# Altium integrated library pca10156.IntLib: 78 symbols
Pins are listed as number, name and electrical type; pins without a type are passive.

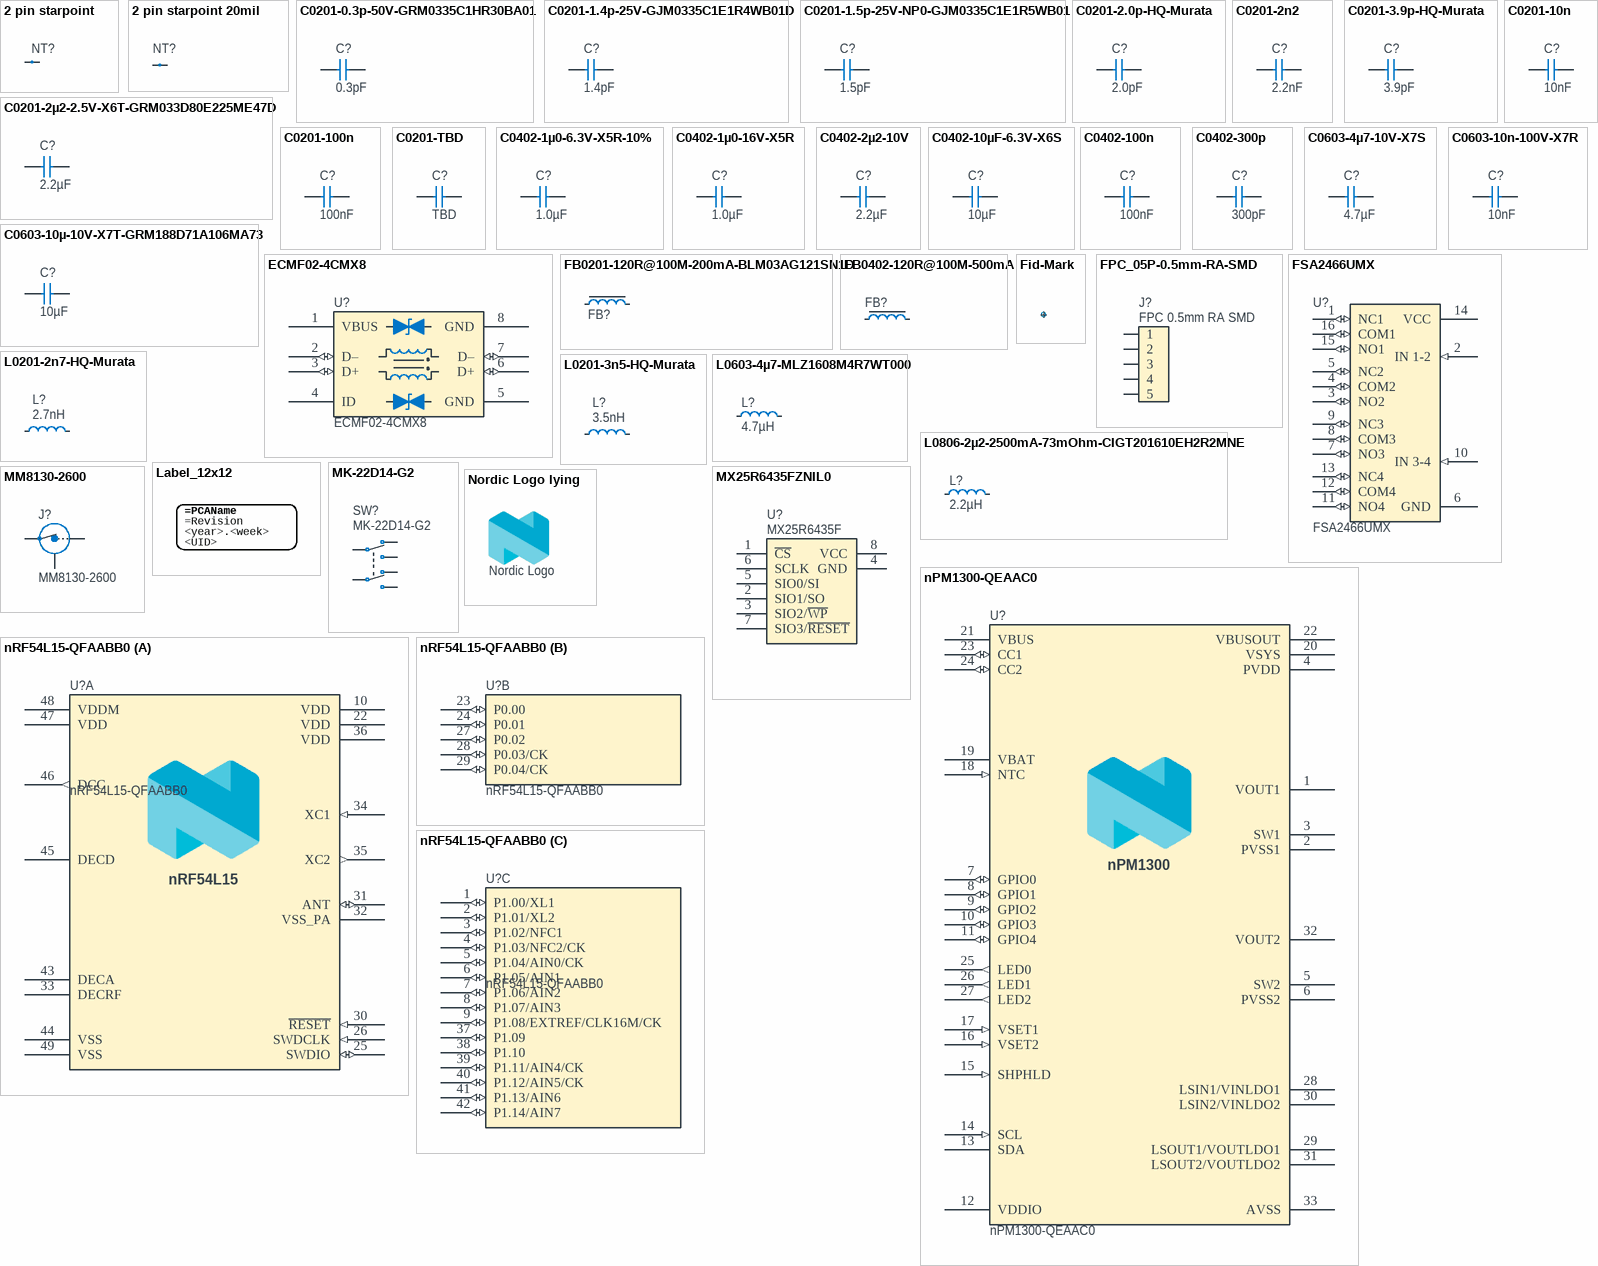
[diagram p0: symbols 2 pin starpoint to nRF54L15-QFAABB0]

## 2 pin starpoint
designator NT?, comment Net tie  (value not drawn)  (net tie, no BOM)
Starpoint; Part Number: 2 pin starpoint; Manufacturer: N.A.; Part number NEMS: 100500603; Pad Count: 2; Component Status: Active; System: Connector
footprint 2 PIN STARPOINT
pins: 1, 2

## 2 pin starpoint 20mil
designator NT?, comment N.A.  (value not drawn)  (net tie, no BOM)
Starpoint; Part Number: 2 pin starpoint 20mil; Part number NEMS: 100500717; Component Status: Active; Pad Count: 2; System: Connector
footprint 2 pin starpoint 20mil
pins: 1, 2

## C0201-0.3p-50V-GRM0335C1HR30BA01
designator C?, comment 0.3pF
Capacitor, C0G, ±0.1pF, 50V; Part Number: C0201-0.3p-50V-GRM0335C1HR30BA01; Manufacturer: Murata; Manufacturer Part Number: GRM0335C1HR30BA01; Part number NEMS: 100200650; Component Status: Active; Pad Count: 2; Artikkelnr Noca: N.A.
footprint CAPC0603X03L_C
pins: 1, 2

## C0201-1.4p-25V-GJM0335C1E1R4WB01D
designator C?, comment 1.4pF
Capacitor, C0G, ±0.05pF, 25V; Part Number: C0201-1.4p-25V-GJM0335C1E1R4WB01D; Manufacturer: Murata; Manufacturer Part Number: GJM0335C1E1R4WB01D; Part number NEMS: 100200553; Pad Count: 2; Artikkelnr Noca: N.A.; Component Status: Active
footprint CAPC0603X03L_C
pins: 1, 2

## C0201-1.5p-25V-NP0-GJM0335C1E1R5WB01
designator C?, comment 1.5pF
Capacitor, NP0, ±0.05pF, 25V, High Q; Part Number: C0201-1.5p-25V-NP0-GJM0335C1E1R5WB01; Manufacturer: Murata; Manufacturer Part Number: GJM0335C1E1R5WB01; Part number NEMS: 100200477; Component Status: Active; Pad Count: 2; Artikkelnr Noca: N.A.
footprint CAPC0603X03L_C
pins: 1, 2

## C0201-2.0p-HQ-Murata
designator C?, comment 2.0pF
Capacitor, NP0, ±0.05pF, 25V; Part Number: C0201-2.0p-HQ-Murata; Manufacturer: Murata; Manufacturer Part Number: GJM0335C1E2R0WB01; Part number IPS: 00000001775; Part number NEMS: 100200419; Component Status: Active; Pad Count: 2; Artikkelnr Noca: N.A.
footprint CAPC0603X03L_C
pins: 1, 2

## C0201-2n2
designator C?, comment 2.2nF
Capacitor, X7R, ±10%, 10V; Part Number: C0201-2n2; Manufacturer: N.A.; Part number IPS: 00000001778; Part number Norautron: 26470002; Part number NEMS: 100200060; Pad Count: 2; Component Status: Active
footprint CAPC0603X03L_C
pins: 1, 2

## C0201-2µ2-2.5V-X6T-GRM033D80E225ME47D
designator C?, comment 2.2µF
Capacitor, Ceramic, 2.2µF 2.5V X6T 0201,±20%; Part Number: C0201-2µ2-2.5V-X6T-GRM033D80E225ME47D; Manufacturer: Murata; Manufacturer Part Number: GRM033R61A225KE47; Part number NEMS: 100200527; Component Status: Active; Pad Count: 2; Note: 2.5V, 20%, X6T; Artikkelnr Noca: N.A.
footprint CAPC0603X03L_C
pins: 1, 2

## C0201-3.9p-HQ-Murata
designator C?, comment 3.9pF
Capacitor, NP0, ±0.05pF, 25V; Part Number: C0201-3.9p-HQ-Murata; Manufacturer: Murata; Manufacturer Part Number: GJM0333C1E3R9WB01; Part number NEMS: 100200424; Component Status: Active; Pad Count: 2; Artikkelnr Noca: N.A.
footprint CAPC0603X03L_C
pins: 1, 2

## C0201-10n
designator C?, comment 10nF
Capacitor, X7R, ±10%; Part Number: C0201-10n; Manufacturer: N.A.; Part number IPS: 00000003480; Part number Norautron: 26621779; Part number NEMS: 100200067; Note: 10V; Pad Count: 2; Component Status: Active
footprint CAPC0603X03L_C
pins: 1, 2

## C0201-100n
designator C?, comment 100nF
Capacitor, X5R, ±10%; Part Number: C0201-100n; Manufacturer: N.A.; Part number IPS: 00000001248, 00000002505; Part number Norautron: 262071862; Part number NEMS: 100200078; Pad Count: 2; Note: 16V; Component Status: Active
footprint CAPC0603X03L_C
pins: 1, 2

## C0201-TBD
designator C?, comment TBD
Chip Cap 0201; Part Number: C0201-TBD; Manufacturer: N.A.; Part number NEMS: 100200002; Component Status: Active; Pad Count: 2; Assembly: Not Mounted
footprint CAPC0603X03L_C
pins: 1, 2

## C0402-1µ0-6.3V-X5R-10%
designator C?, comment 1.0µF
Capacitor, X5R, ±10%, 6.3V; Part Number: C0402-1µ0-6.3V-X5R-10%; Manufacturer: N.A.; Part number Norautron: 26207137; Part number NEMS: 100200498; Pad Count: 2; Component Status: Active
footprint CAPC1005X04L
pins: 1, 2

## C0402-1µ0-16V-X5R
designator C?, comment 1.0µF
Capacitor, Ceramic, X5R, ±10%, 16V; Part Number: C0402-1µ0-16V-X5R; Manufacturer: Murata; Manufacturer Part Number: GRT155R61C105KE01D; Part number NEMS: 100200452; Component Status: Active; Pad Count: 2; Artikkelnr Noca: N.A.
footprint CAPC1005X04L
pins: 1, 2

## C0402-2µ2-10V
designator C?, comment 2.2µF
Capacitor, X5R, ±10%; Part Number: C0402-2µ2-10V; Manufacturer: N.A.; Part number NEMS: 100200376; Component Status: Active; Pad Count: 2; Note: 10V
footprint CAPC1005X04L
pins: 1, 2

## C0402-10µF-6.3V-X6S
designator C?, comment 10µF
Capacitor, X6S, ±20%, 6.3V; Part Number: C0402-10µF-6.3V-X6S; Manufacturer: N.A.; Part number NEMS: 100200478; Component Status: Active; Pad Count: 2
footprint CAPC1005X04L
pins: 1, 2

## C0402-100n
designator C?, comment 100nF
Capacitor, X7R, ±10%; Part Number: C0402-100n; Manufacturer: N.A.; Part number IPS: 00000005296; Part number NEMS: 100200184; Component Status: Active; Pad Count: 2; Note: 16V; Artikkelnr Noca: 20039200; Assembly: Not Mounted
footprint CAPC1005X04L
pins: 1, 2

## C0402-300p
designator C?, comment 300pF
Capacitor, C0G, ±5%, 50V; Part Number: C0402-300p; Manufacturer: N.A.; Part number IPS: 00000007788; Part number NEMS: 100200155; Artikkelnr Noca: 20020004; Pad Count: 2; Component Status: Active
footprint CAPC1005X04L
pins: 1, 2

## C0603-4µ7-10V-X7S
designator C?, comment 4.7µF
Capacitor, X7S, ±10%, 10V; Part Number: C0603-4µ7-10V-X7S; Manufacturer: N.A.; Part number IPS: 00000001779; Part number NEMS: 100200351; Pad Count: 2; Artikkelnr Noca: 20030013; Component Status: Active
footprint CAPC1608X06L
pins: 1, 2

## C0603-10n-100V-X7R
designator C?, comment 10nF
Capacitor, X7R, ±10%, 100V; Part Number: C0603-10n-100V-X7R; Manufacturer: Murata; Manufacturer Part Number: GCM188R72A103KA37D; Part number NEMS: 100200349; Component Status: Active; Pad Count: 2; Artikkelnr Noca: N.A.
footprint CAPC1608X06L
pins: 1, 2

## C0603-10µ-10V-X7T-GRM188D71A106MA73
designator C?, comment 10µF
Capacitor, X7T, ±20%, 10V; Part Number: C0603-10µ-10V-X7T-GRM188D71A106MA73; Manufacturer: Murata; Manufacturer Part Number: GRM188D71A106MA73; Part number IPS: 00000004696; Part number NEMS: 100200414; Component Status: Active; Pad Count: 2; Note: 10VDC; Artikkelnr Noca: N.A.
footprint CAPC1608X06L
pins: 1, 2

## ECMF02-4CMX8
designator U?
2 Line Common mode filter with ESD protection for USB 2.0 interface; Manufacturer: STMicroelectronics; Part number NEMS: 100800034; Component Status: Active; Pad Count: 8; Note: N.A.
footprint UFDFN50P120X250X55-8N
pins: 1 VBUS (power), 2 D– (io), 3 D+ (io), 4 ID, 5 GND (power), 6 D+ (io), 7 D– (io), 8 GND (power)

## FB0201-120R@100M-200mA-BLM03AG121SN1D
designator FB?, comment 120R/0.2A  (value not drawn)
Ferrite Bead, 120 Ohm @ 100MHz, 200mA, 500 mOhm Max; Part Number: FB0201-120R@100M-200mA-BLM03AG121SN1D; Manufacturer: Murata; Manufacturer Part Number: BLM03AG121SN1D; Part number NEMS: 100300419; Component Status: Active; Pad Count: 2; Artikkelnr Noca: N.A.
footprint INDC0603X03L_C
pins: 1, 2

## FB0402-120R@100M-500mA
designator FB?, comment 120R/0.55A  (value not drawn)
Ferrite Bead, 120 Ohm @ 100MHz, 500mA, 250 mOhm Max; Part Number: FB0402-120R@100M-500mA; Manufacturer: Murata; Manufacturer Part Number: BLM15AG121SN1D; Part number IPS: 00000009954; Part number Norautron: 265230631; Part number NEMS: 100300099; Note: Chip EMIFIL Inductor Type Chip Ferrite Bead; Artikkelnr Noca: 33029317; Pad Count: 2; Component Status: Active
footprint INDC1005X04L
pins: 1, 2

## Fid-Mark
designator Fid?, comment Fiducial mark  (value not drawn)
Part Number: Fid-Mark; Manufacturer: N.A.; Part number NEMS: 100500073; Value: N.A.; Pad Count: 1; Component Status: Active; System: Connector
footprint Fiducial

## FPC_05P-0.5mm-RA-SMD
designator J?, comment FPC 0.5mm RA SMD
0.5mm FPC, 5P,Right Angle SMT,Double Contact,H=1.2mm,White, Tin plated; Part Number: FPC_05P-0.5mm-RA-SMD; Manufacturer: WCON; Manufacturer Part Number: 5141-05RZDNWR03; Part number NEMS: 100500528; Note: (Replaced 5141-05RZDNWR02); Artikkelnr Noca: N.A.; Pad Count: 7; Component Status: Active; System: Connector
footprint FPC_05P-0.5mm-RA-SMD
pins: 1, 2, 3, 4, 5

## FSA2466UMX
designator U?
Data / Audio Low-Voltage Dual DPDT Analog Switch; Manufacturer: ON Semiconductor; Part number IPS: 00000009986; Part number Norautron: 26500608; Part number NEMS: 101900422; Note: N.A.; Artikkelnr Noca: 15070069; Pad Count: 16; Component Status: Active
footprint XQFN40P180X260X50-16N
pins: 1 NC1 (io), 2 IN 1-2 (in), 3 NO2 (io), 4 COM2 (io), 5 NC2 (io), 6 GND (power), 7 NO3 (io), 8 COM3 (io), 9 NC3 (io), 10 IN 3-4 (in), 11 NO4 (io), 12 COM4 (io), 13 NC4 (io), 14 VCC (power), 15 NO1 (io), 16 COM1 (io)
1 alternate drawing of the same symbol

## L0201-2n7-HQ-Murata
designator L?, comment 2.7nH
Inductor, 600mA, ±0.1ｎH, 120mOhm; Part Number: L0201-2n7-HQ-Murata; Manufacturer: Murata; Manufacturer Part Number: LQP03HQ2N7B02; Part number IPS: 00000001753; Part number NEMS: 100300214; Component Status: Active; Pad Count: 2; Note: -55°C ~ 125°C; Artikkelnr Noca: N.A.
footprint INDC0603X03L_C
pins: 1, 2

## L0201-3n5-HQ-Murata
designator L?, comment 3.5nH
Inductor, 500mA, ±0.1ｎH, 170mOhm; Part Number: L0201-3n5-HQ-Murata; Manufacturer: Murata; Manufacturer Part Number: LQP03HQ3N5B02; Part number NEMS: 100300222; Component Status: Active; Pad Count: 2; Note: -55°C ~ 125°C; Artikkelnr Noca: N.A.
footprint INDC0603X03L_C
pins: 1, 2

## L0603-4µ7-MLZ1608M4R7WT000
designator L?, comment 4.7µH
Inductor, 120mA, ±20%, 0.65R; Part Number: L0603-4µ7-MLZ1608M4R7WT000; Manufacturer: TDK Corporation; Manufacturer Part Number: MLZ1608M4R7WT000; Part number NEMS: 100300440; Component Status: Active; Pad Count: 2; Note: Power Inductor ±20%; Artikkelnr Noca: N.A.
footprint INDC1608X06L
pins: 1, 2

## L0806-2µ2-2500mA-73mOhm-CIGT201610EH2R2MNE
designator L?, comment 2.2µH
Inductor, Irms=2.5A, Isat=2.9A, ±20%, DCR=73mΩ; Part Number: L0806-2µ2-2500mA-73mOhm-CIGT201610EH2R2MNE; Manufacturer: Samsung Electro-Mechanics America; Manufacturer Part Number: CIGT201610EH2R2MNE; Part number Norautron: 26521789; Part number NEMS: 100300400; Component Status: Active; Pad Count: 2; Note: Unshielded Thin Film Inductor; Artikkelnr Noca: N.A.
footprint INDC2016X10N
pins: 1, 2

## Label_12x12
designator LABEL?, comment 12x12mm  (value not drawn)
PCA version label, stick-on, 12x12mm; Part Number: Label_12x12; Manufacturer: Ellco Etikett; Manufacturer Part Number: A33512‐01; Part number NEMS: 101200028; Component Status: Active; Pad Count: 0; Note: N.A.
footprint LabelSilk_12x12

## MK-22D14-G2
designator SW?
Slide Switch DPDT; Manufacturer: HUA-JIE CORP.; Part number NEMS: 101500131; Note: N.A.; Pad Count: 6; Component Status: Active
footprint MK-22D14-G2
pins: 1 N.O-1, 2 COM-1, 3 N.C-1, 4 N.O-2, 5 COM-2, 6 N.C-2

## MM8130-2600
designator J?
Coaxial Connector with Switch; Manufacturer: Murata; Part number IPS: 00000009955; Part number Norautron: 26030338; Part number NEMS: 100500400; Component Status: Active; Pad Count: 3; Note: N.A.; Artikkelnr Noca: 55029011
footprint COAXIAL-SWF
pins: 1 IN, 2 Shield, 3 OUT

## MX25R6435FZNIL0
designator U?, comment MX25R6435F
Ultra low power, 64M-bit, serial multi I/O flash memory; Part Number: MX25R6435FZNIL0; Manufacturer: Macronix; Part number IPS: 00000004370; Part number NEMS: 101900438; Note: N.A.; Artikkelnr Noca: 15020015; Pad Count: 8; Component Status: Active
footprint SON127P600X80_HS-9N
pins: 1 ~{CS}, 2 SIO1/SO, 3 SIO2/~{WP}, 4 GND, 5 SIO0/SI, 6 SCLK, 7 SIO3/~{RESET}, 8 VCC, 9 GND hidden to GND

## Nordic Logo lying
designator LOGO?, comment Nordic Logo  (no BOM)
Nordic logo lying; Manufacturer: N.A.; Part number NEMS: 101100001; Component Status: Active; Pad Count: 0
footprint NORDIC_LOGO_LYING

## nPM1300-QEAAC0
designator U?
Li-Ion/Li-Polymer USB-C battery charger with high efficiency buck regulators, LDOs or load switches, LED drivers, TWI and VBUSOUT; Manufacturer: Nordic Semiconductor; Part number NEMS: 102000306; Component Status: Active; Pad Count: 33; Note: Production version; Artikkelnr Noca: N.A.
footprint Nordic_QFN50P500X500X90-33N
pins: 1 VOUT1 (power), 2 PVSS1 (power), 3 SW1 (power), 4 PVDD (power), 5 SW2 (power), 6 PVSS2 (power), 7 GPIO0 (io), 8 GPIO1 (io), 9 GPIO2 (io), 10 GPIO3 (io), 11 GPIO4 (io), 12 VDDIO (power), 13 SDA (oc), 14 SCL (in), 15 SHPHLD (in), 16 VSET2 (in), 17 VSET1 (in), 18 NTC (in), 19 VBAT, 20 VSYS (power), 21 VBUS (power), 22 VBUSOUT (power), 23 CC1 (io), 24 CC2 (io), 25 LED0 (out), 26 LED1 (out), 27 LED2 (out), 28 LSIN1/VINLDO1 (power), 29 LSOUT1/VOUTLDO1 (power), 30 LSIN2/VINLDO2 (power), 31 LSOUT2/VOUTLDO2 (power), 32 VOUT2 (power), 33 AVSS (power)

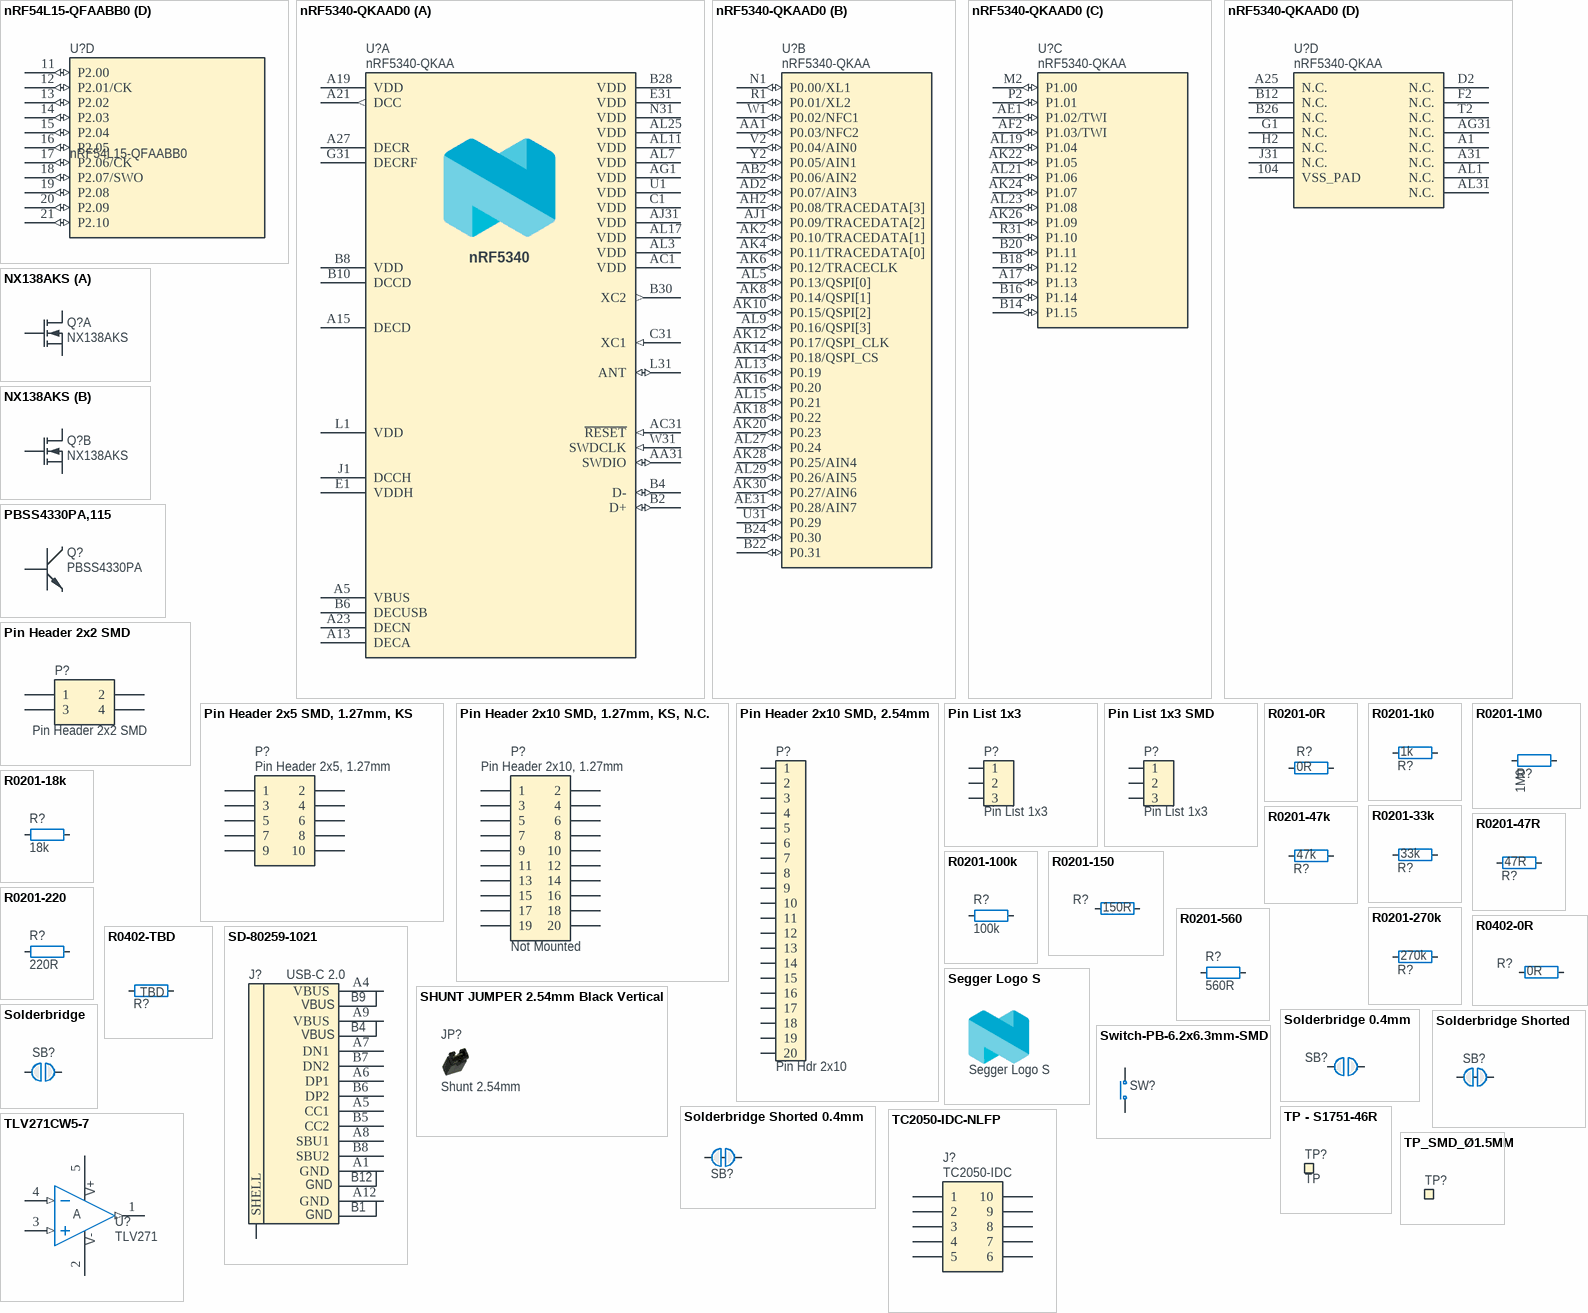
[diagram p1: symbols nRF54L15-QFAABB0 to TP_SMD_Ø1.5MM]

## nRF54L15-QFAABB0
designator U?
Multi-protocol Bluetooth Low Energy, IEEE 802.15.4, ANT and 2.4GHz proprietary system-on-chip; Manufacturer: Nordic Semiconductor; Component Status: Active; Pad Count: 49; Note: N.A.
footprint QFN40P600X600X90-48N
part A pins: 10 VDD (power), 22 VDD (power), 25 SWDIO (io), 26 SWDCLK (in), 30 ~{RESET} (in), 31 ANT (io), 32 VSS_PA (power), 33 DECRF (power), 34 XC1 (in), 35 XC2 (out), 36 VDD (power), 43 DECA (power), 44 VSS (power), 45 DECD (power), 46 DCC (out), 47 VDD (power), 48 VDDM (power), 49 VSS (power)
part B pins: 23 P0.00 (io), 24 P0.01 (io), 27 P0.02 (io), 28 P0.03/CK (io), 29 P0.04/CK (io)
part C pins: 1 P1.00/XL1 (io), 2 P1.01/XL2 (io), 3 P1.02/NFC1 (io), 4 P1.03/NFC2/CK (io), 5 P1.04/AIN0/CK (io), 6 P1.05/AIN1 (io), 7 P1.06/AIN2 (io), 8 P1.07/AIN3 (io), 9 P1.08/EXTREF/CLK16M/CK (io), 37 P1.09 (io), 38 P1.10 (io), 39 P1.11/AIN4/CK (io), 40 P1.12/AIN5/CK (io), 41 P1.13/AIN6 (io), 42 P1.14/AIN7 (io)
part D pins: 11 P2.00 (io), 12 P2.01/CK (io), 13 P2.02 (io), 14 P2.03 (io), 15 P2.04 (io), 16 P2.05 (io), 17 P2.06/CK (io), 18 P2.07/SWO (io), 19 P2.08 (io), 20 P2.09 (io), 21 P2.10 (io)

## nRF5340-QKAAD0
designator U?, comment nRF5340-QKAA
Multi-protocol Bluetooth Low Energy, IEEE 802.15.4, ANT and 2.4GHz proprietary system-on-chip; Part Number: nRF5340-QKAAD0; Manufacturer: Nordic Semiconductor; Part number Norautron: NOD26470035; Part number NEMS: 102000216; Pad Count: 98; Note: N.A.; Component Status: Active
footprint AQFN40P700X700X85_HS-99N
part A pins: A5 VBUS (power), A13 DECA (power), A15 DECD (power), A19 VDD (power), A21 DCC (out), A23 DECN (power), A27 DECR (power), AA31 SWDIO (io), AC1 VDD (power), AC31 ~{RESET} (in), AG1 VDD (power), AJ31 VDD (power), AL3 VDD (power), AL7 VDD (power), AL11 VDD (power), AL17 VDD (power), AL25 VDD (power), B2 D+ (io), B4 D- (io), B6 DECUSB (power), B8 VDD (power), B10 DCCD (power), B28 VDD (power), B30 XC2 (out), C1 VDD (power), C31 XC1 (in), E1 VDDH (power), E31 VDD (power), G31 DECRF (power), J1 DCCH (power), L1 VDD (power), L31 ANT (io), N31 VDD (power), U1 VDD (power), W31 SWDCLK (in)
part B pins: AA1 P0.03/NFC2 (io), AB2 P0.06/AIN2 (io), AD2 P0.07/AIN3 (io), AE31 P0.28/AIN7 (io), AH2 P0.08/TRACEDATA[3] (io), AJ1 P0.09/TRACEDATA[2] (io), AK2 P0.10/TRACEDATA[1] (io), AK4 P0.11/TRACEDATA[0] (io), AK6 P0.12/TRACECLK (io), AK8 P0.14/QSPI[1] (io), AK10 P0.15/QSPI[2] (io), AK12 P0.17/QSPI_CLK (io), AK14 P0.18/QSPI_CS (io), AK16 P0.20 (io), AK18 P0.22 (io), AK20 P0.23 (io), AK28 P0.25/AIN4 (io), AK30 P0.27/AIN6 (io), AL5 P0.13/QSPI[0] (io), AL9 P0.16/QSPI[3] (io), AL13 P0.19 (io), AL15 P0.21 (io), AL27 P0.24 (io), AL29 P0.26/AIN5 (io), B22 P0.31 (io), B24 P0.30 (io), N1 P0.00/XL1 (io), R1 P0.01/XL2 (io), U31 P0.29 (io), V2 P0.04/AIN0 (io), W1 P0.02/NFC1 (io), Y2 P0.05/AIN1 (io)
part C pins: A17 P1.13 (io), AE1 P1.02/TWI (io), AF2 P1.03/TWI (io), AK22 P1.05 (io), AK24 P1.07 (io), AK26 P1.09 (io), AL19 P1.04 (io), AL21 P1.06 (io), AL23 P1.08 (io), B14 P1.15 (io), B16 P1.14 (io), B18 P1.12 (io), B20 P1.11 (io), M2 P1.00 (io), P2 P1.01 (io), R31 P1.10 (io)
part D pins: 104 VSS_PAD (power), A1 N.C., A25 N.C., A31 N.C., AG31 N.C., AL1 N.C., AL31 N.C., B12 N.C., B26 N.C., D2 N.C., F2 N.C., G1 N.C., H2 N.C., J31 N.C., T2 N.C.

## NX138AKS
designator Q?
MOSFET 2N-CH 60V 0.17A TSSOP6 (SOT363); Manufacturer: Nexperia; Manufacturer Part Number: NX138AKSX; Part number NEMS: 101300207; Component Status: Active; Pad Count: 6; Note: N.A.
footprint TSSOP6
part A pins: 1 S1, 2 G1, 6 D1
part B pins: 3 D2, 4 S2, 5 G2

## PBSS4330PA,115
designator Q?, comment PBSS4330PA
30V, 3A, 2.1W, G=270, NPN Transistor; Part Number: PBSS4330PA,115; Manufacturer: Nexperia; Part number NEMS: 101300184; Component Status: Active; Pad Count: 3; Note: N.A.
footprint DFN105P200X65-3N_v2
pins: 1 B, 2 E (power), 3 C (power)

## Pin Header 2x2 SMD
designator P?
Pin Header 2x2, SMD, 2.54mm (100mil); Manufacturer: WCON; Manufacturer Part Number: 1125-1202S0M116CR03; Part number NEMS: 100500770; Component Status: Active; Pad Count: 4; Note: N.A.; System: Connector
footprint HDR_2x2-SMD
pins: 1, 2, 3, 4

## Pin Header 2x5 SMD, 1.27mm, KS
designator P?, comment Pin Header 2x5, 1.27mm
Pin Header 2x5, 1.27mm (50mil), SMD, Keying Shroud; Part Number: Pin Header 2x5 SMD, 1.27mm, KS; Manufacturer: WCON; Manufacturer Part Number: 3132-10MS0BK00R5; Part number NEMS: 100500261; Note: (Replaced 3132-10MS0BK00R1); Artikkelnr Noca: N.A.; Pad Count: 10; Component Status: Active; System: Connector
footprint HDR_2x5-SMD-1.27mm-K
pins: 1, 2, 3, 4, 5, 6, 7, 8, 9, 10

## Pin Header 2x10 SMD, 1.27mm, KS, N.C.
designator P?, comment Pin Header 2x10, 1.27mm  Assembly: Not Mounted
Pin Header 2x10, 1.27mm (50mil), SMD, Keying Shroud; Part Number: Pin Header 2x10 SMD, 1.27mm, KS, N.C.; Manufacturer: WCON; Manufacturer Part Number: 3132-20MS0BK00R1; Part number NEMS: 100500279; Note: N.A.; Pad Count: 20; Component Status: Active; System: Connector
footprint HDR_2x10-SMD-1.27mm-NC
pins: 1, 2, 3, 4, 5, 6, 7, 8, 9, 10, 11, 12, 13, 14, 15, 16, 17, 18, 19, 20

## Pin Header 2x10 SMD, 2.54mm
designator P?, comment Pin Hdr 2x10
Pin Header 2x10, 2.54mm (100mil) SMD; Part Number: Pin Header 2x10 SMD, 2.54mm; Manufacturer: WCON; Manufacturer Part Number: 1125-1210S0M116CR09; Part number NEMS: 100500738; Pad Count: 20; Artikkelnr Noca: N.A.; Component Status: Active; System: Connector
footprint HDR_2x10-SMD
pins: 1, 2, 3, 4, 5, 6, 7, 8, 9, 10, 11, 12, 13, 14, 15, 16, 17, 18, 19, 20
1 alternate drawing of the same symbol

## Pin List 1x3
designator P?
Pin List 1x3, 2.54mm (100mil); Manufacturer: N.A.; Part number NEMS: 100500304; Component Status: Active; Pad Count: 3; Artikkelnr Noca: 56019041; Assembly: Not Mounted; System: Connector
footprint LIST_1x3
pins: 1, 2, 3

## Pin List 1x3 SMD
designator P?, comment Pin List 1x3
Pin List 1x3, 2.54mm (100mil), SMD; Part Number: Pin List 1x3 SMD; Manufacturer: WCON; Manufacturer Part Number: 1125-1103S0M116CR04; Part number Norautron: 26470016; Part number NEMS: 100500306; Note: N.A.; Pad Count: 3; Component Status: Active; System: Connector
footprint LIST_1x3_SMD
pins: 1, 2, 3

## R0201-0R
designator R?, comment 0R
Resistor, ±5%, 0.05W; Part Number: R0201-0R; Manufacturer: N.A.; Part number IPS: 00000003245; Part number NEMS: 100100001; Component Status: Active; Pad Count: 2; Note: Chip Res 5%
footprint RESC0603X03L_C
pins: 1, 2

## R0201-1k0
designator R?, comment 1k
Resistor, ±1%, 0.05W; Part Number: R0201-1k0; Manufacturer: N.A.; Part number IPS: 00000005786; Part number NEMS: 100100043; Component Status: Active; Pad Count: 2; Note: Chip Res 1%
footprint RESC0603X03L_C
pins: 1, 2

## R0201-1M0
designator R?, comment 1M0
Resistor, ±1%, 0.05W; Part Number: R0201-1M0; Manufacturer: N.A.; Part number IPS: 00000001418; Part number Norautron: 26107108; Part number NEMS: 100100093; Component Status: Active; Pad Count: 2; Note: Chip Res 1%
footprint RESC0603X03L_C
pins: 1, 2

## R0201-18k
designator R?, comment 18k
Resistor, ±1%, 0.05W; Part Number: R0201-18k; Manufacturer: N.A.; Part number IPS: 00000001707; Part number NEMS: 100100069; Component Status: Active; Pad Count: 2; Note: Chip Res 1%; Assembly: Not Mounted
footprint RESC0603X03L_C
pins: 1, 2

## R0201-33k
designator R?, comment 33k
Resistor, ±1%, 0.05W; Part Number: R0201-33k; Manufacturer: N.A.; Part number IPS: 00000001708; Part number NEMS: 100100073; Component Status: Active; Pad Count: 2; Note: Chip Res 1%
footprint RESC0603X03L_C
pins: 1, 2

## R0201-47k
designator R?, comment 47k
Resistor, ±1%, 0.05W; Part Number: R0201-47k; Manufacturer: N.A.; Part number IPS: 00000001423; Part number NEMS: 100100076; Component Status: Active; Pad Count: 2; Note: Chip Res 1%
footprint RESC0603X03L_C
pins: 1, 2

## R0201-47R
designator R?, comment 47R
Resistor, ±1%, 0.05W; Part Number: R0201-47R; Manufacturer: N.A.; Part number IPS: 00000004794; Part number Norautron: 26108300; Part number NEMS: 100100022; Component Status: Active; Pad Count: 2; Note: Chip Res 1%
footprint RESC0603X03L_C
pins: 1, 2

## R0201-100k
designator R?, comment 100k
Resistor, ±1%, 0.05W; Part Number: R0201-100k; Manufacturer: N.A.; Part number IPS: 00000001419; Part number Norautron: 26108487; Part number NEMS: 100100080; Note: Chip Res 1%; Pad Count: 2; Component Status: Active
footprint RESC0603X03L_C
pins: 1, 2

## R0201-150
designator R?, comment 150R
Resistor, ±1%, 0.05W; Part Number: R0201-150; Manufacturer: N.A.; Part number IPS: 00000001420; Part number NEMS: 100100029; Note: Chip Res 1%; Pad Count: 2; Component Status: Active
footprint RESC0603X03L_C
pins: 1, 2

## R0201-220
designator R?, comment 220R
Resistor, ±1%, 0.05W; Part Number: R0201-220; Manufacturer: N.A.; Part number IPS: 00000000863; Part number Norautron: 26107014; Part number NEMS: 100100032; Note: Chip Res 1%; Pad Count: 2; Component Status: Active
footprint RESC0603X03L_C
pins: 1, 2

## R0201-270k
designator R?, comment 270k
Resistor, ±1%, 0.05W; Part Number: R0201-270k; Manufacturer: N.A.; Part number IPS: 00000004317; Part number NEMS: 100100086; Component Status: Active; Pad Count: 2; Note: Chip Res 1%
footprint RESC0603X03L_C
pins: 1, 2

## R0201-560
designator R?, comment 560R
Resistor, ±1%, 0.05W; Part Number: R0201-560; Manufacturer: N.A.; Part number NEMS: 100100038; Note: Chip Res 1%; Pad Count: 2; Component Status: Active
footprint RESC0603X03L_C
pins: 1, 2

## R0402-0R
designator R?, comment 0R
Resistor, ±5%, 0.063W; Part Number: R0402-0R; Manufacturer: N.A.; Part number IPS: 00000007128; Part number NEMS: 100100109; Component Status: Active; Pad Count: 2; Note: Chip Res 5%; Artikkelnr Noca: 27049000; Assembly: Not Mounted
footprint RESC1005X04L
pins: 1, 2

## R0402-TBD
designator R?, comment TBD
Chip Res 0402; Part Number: R0402-TBD; Manufacturer: N.A.; Part number NEMS: 100100282; Component Status: Active; Pad Count: 2; Assembly: Not Mounted
footprint RESC1005X04L
pins: 1, 2

## SD-80259-1021
designator J?, comment USB-C 2.0
USB-C Receptacle, 16 Pin, USB 2.0; Part Number: SD-80259-1021; Manufacturer: Bellweather Electronic Corp.; Part number NEMS: 100500830; Component Status: Active; Pad Count: 16; Note: N.A.; System: Connector
footprint SD-80259-001
pins: A1 GND (power), A4 VBUS (power), A5 CC1, A6 DP1, A7 DN1, A8 SBU1, A9 VBUS (power), A12 GND (power), B5 CC2, B6 DP2, B7 DN2, B8 SBU2, SHLD SHELL (power)

## Segger Logo S
designator LOGO?  (no BOM)
Segger logo, small size; Manufacturer: N.A.; Part number NEMS: 101100004; Component Status: Active; Pad Count: 0
footprint SEGGER_LOGO_S

## SHUNT JUMPER 2.54mm Black Vertical
designator JP?, comment Shunt 2.54mm
Shunt Jumper 2.54mm Black, open top; Part Number: SHUNT JUMPER 2.54mm Black Vertical; Manufacturer: WCON; Manufacturer Part Number: 3710-6001OS0B05; Part number NEMS: 100500728; Pad Count: 2; Note: N.A.; Component Status: Active; System: Connector
footprint Shunt_2.54mm_Vertical

## Solderbridge
designator SB?  (value not drawn)  (no BOM)
Manufacturer: N.A.; Part number NEMS: 100500458; Pad Count: 2; Component Status: Active; System: Connector
footprint Solderbridge
pins: 1 0, 2 1

## Solderbridge 0.4mm
designator SB?, comment Solderbridge  (value not drawn)  (no BOM)
Part Number: Solderbridge 0.4mm; Manufacturer: N.A.; Part number NEMS: 100500560; Component Status: Active; Pad Count: 2; System: Connector
footprint Solderbridge_0.4
pins: 1 0, 2 1

## Solderbridge Shorted
designator SB?, comment Solderbridge  (value not drawn)  (net tie, no BOM)
Shorted Solderbridge; Part Number: Solderbridge Shorted; Manufacturer: N.A.; Part number NEMS: 100500459; Pad Count: 2; Component Status: Active; System: Connector
footprint Solderbridge_Shorted
pins: 1 0, 2 1

## Solderbridge Shorted 0.4mm
designator SB?, comment Solderbridge  (value not drawn)  (net tie, no BOM)
Shorted Solderbridge; Part Number: Solderbridge Shorted 0.4mm; Manufacturer: N.A.; Part number NEMS: 100500561; Component Status: Active; Pad Count: 2; System: Connector
footprint Solderbridge_SHORTED_0.4
pins: 1 0, 2 1

## Switch-PB-6.2x6.3mm-SMD
designator SW?, comment PB SW  (value not drawn)
Tactile Switch, SPNO, SMD, 160gf, 6.2x6.3x2.5mm; Part Number: Switch-PB-6.2x6.3mm-SMD; Manufacturer: Dailywell; Manufacturer Part Number: TS604VM1-025BR-R; Part number IPS: 00000007812; Part number NEMS: 101500001, 101500133; Note: N.A.; Artikkelnr Noca: 50019106; Pad Count: 4; Component Status: Active
footprint Switch-PB-6.2x6.3mm-SMD
pins: 1 N.O, 2 COM

## TC2050-IDC-NLFP
designator J?, comment TC2050-IDC  (no BOM)
CBL PLUG-OF-NAILS 10-PIN; Part Number: TC2050-IDC-NLFP; Manufacturer: Tag-Connect LLC; Part number NEMS: 100500463; Artikkelnr Noca: N.A.; Pad Count: 10; Component Status: Active; System: Connector
footprint TC2050-IDC-NLFP
pins: 1, 2, 3, 4, 5, 6, 7, 8, 9, 10

## TLV271CW5-7
designator U?, comment TLV271
Dual rail to rail CMOS Amplifier; Part Number: TLV271CW5-7; Manufacturer: Diodes Incorporated; Part number NEMS: 101900398; Component Status: Active; Pad Count: 5; Note: N.A.
footprint SOT95P280X145-5N
pins: 1 OUT (out), 2 VSS (power), 3 IN+ (in), 4 IN- (in), 5 VDD (power)
1 alternate drawing of the same symbol

## TP - S1751-46R
designator TP?, comment TP
PC TEST POINT TIN SMD L; Part Number: TP - S1751-46R; Manufacturer: Harwin; Manufacturer Part Number: S1751-46R; Part number NEMS: 100500525; Component Status: Active; Pad Count: 1; Note: N.A.
footprint S1751
pins: 1

## TP_SMD_Ø1.5MM
designator TP?, comment Ø1.5mm,SMD  (value not drawn)  (no BOM)
1.5mm circular SMD testpad; Part Number: TP_SMD_Ø1.5MM; Manufacturer: Nordic Semiconductor; Manufacturer Part Number: N.A.; Part number NEMS: 100500477; Pad Count: 1; Component Status: Active
footprint TP_SMD_D1.5mm
pins: 1

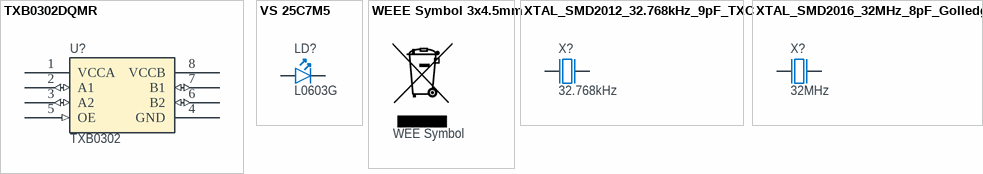
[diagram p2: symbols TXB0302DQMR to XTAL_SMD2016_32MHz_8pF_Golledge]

## TXB0302DQMR
designator U?, comment TXB0302
2-bit bidirectional voltage-level translator with automatic direction sensing; Part Number: TXB0302DQMR; Manufacturer: Texas Instruments; Part number NEMS: 101900198; Component Status: Active; Pad Count: 8; Note: Fully Symmetric Supply Voltages; Artikkelnr Noca: N.A.
footprint XFDFN40P180X120X40-8M
pins: 1 VCCA (power), 2 A1 (io), 3 A2 (io), 4 GND (power), 5 OE (in), 6 B2 (io), 7 B1 (io), 8 VCCB (power)

## VS 25C7M5
designator LD?, comment L0603G
LED, Green, 0603, 573nm, Vf=2.0V, 24mcd, - 40 to +85°C; Part Number: VS 25C7M5; Manufacturer: Victory Electronics; Part number IPS: 00000001274, 00000009961; Part number Norautron: 26313411; Part number NEMS: 101400097; Pad Count: 2; Note: N.A.; Artikkelnr Noca: 13019193; Component Status: Active
footprint LED_0603_G
pins: 1 C, 2 A

## WEEE Symbol 3x4.5mm
designator LOGO?, comment WEE Symbol  (no BOM)
WEEE Directive symbol; Part Number: WEEE Symbol 3x4.5mm; Manufacturer: N.A.; Part number NEMS: 101100006; Component Status: Active; Pad Count: 0
footprint WEE_3x4.5mm

## XTAL_SMD2012_32.768kHz_9pF_TXC
designator X?, comment 32.768kHz
XTAL SMD 2012, 32.768kHz, 9pF, ±20ppm; Part Number: XTAL_SMD2012_32.768kHz_9pF_TXC; Manufacturer: TXC Corporation; Manufacturer Part Number: 9HT11-32.768KDZC-T; Part number NEMS: 101600107; Component Status: Active; Pad Count: 2; Note: XTAL SMD 32.768kHz; Artikkelnr Noca: N.A.
footprint XTAL_2012
pins: 1 inp, 2 out

## XTAL_SMD2016_32MHz_8pF_Golledge
designator X?, comment 32MHz
XTAL SMD 2016, 32MHz, Cl=8pF, Tol: ±10ppm, Stab: ±15ppm; Part Number: XTAL_SMD2016_32MHz_8pF_Golledge; Manufacturer: Golledge; Manufacturer Part Number: MP06003; Part number IPS: 00000001431; Part number Norautron: N.A.; Part number NEMS: 101600041; Component Status: Active; Pad Count: 4; Note: XTAL SMD 32.000MHz; Artikkelnr Noca: 22010050
footprint BT-XTAL_2016
pins: 1 inp, 2 GND hidden to GND, 3 out, 4 GND hidden to GND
